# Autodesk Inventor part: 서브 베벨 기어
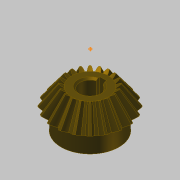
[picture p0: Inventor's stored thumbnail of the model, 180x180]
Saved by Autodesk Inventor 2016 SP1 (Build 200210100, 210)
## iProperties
Created: 2016-04
Part Number: 서브 베벨 기어
Material: 강철, 탄소
Document SubType Name: Modeling
Designer: mdu
Categories: <?xml version="1.0" encoding="UTF-16"?> <MemberInstance><Categories><FamilyTemplate><FamilyTemplateParameter ValueType="xs:double" Id="1" ObjectReferenceKey="da
Mass: 135.037 g
Surface Area: 63.6518 cm^2
Volume: 17.1585 cm^3
Density: 7.87 g/cm^3
Appearance: 얼룩무늬
CustomPartVersion: 1
Author: mdu
Revision Number: 1
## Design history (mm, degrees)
node "맨 위 점"
node "메쉬 평면2"
sketch "톱니 본체 스케치"
  geometry: L1 (0, 0)-(18.003, -31.331); L2 (18.003, -31.331)-(21.664, -28.891); L3 (21.664, -28.891)-(0, 0); L4 (20, -30)-(0, 0); L5 (10.813, -18.818)-(13.012, -17.352); L6 (18.003, -31.331)-(10.813, -18.818); L7 (21.664, -28.891)-(13.012, -17.352); L8 (0, -39.387)-(0, 6.564) reference; L9 (0, -30)-(21.664, -30)
  constraints: 16 end point, 4 point on line, 3 perpendicular, 2 collinear, 1 horizontal alignment, 1 vertical alignment
  dimensions: "d0" = 40 diameter of L4.start L8 (= da_de); "d1" = 36.00616 diameter of L1.end L8 (= da_dfe); "d2" = 43.3282 diameter of L2.end L8 (= da_dae); "d3" = 14.4 distance between parallel lines of L2 L5 (= da_b); "d4" = 28.8906 vertical distance of L2.end L1.start (= da_ve)
revolve "톱니 본체" sketch "톱니 본체 스케치" stored, may be unused: angle "d5" = 90 deg
node "시작점"
node "톱니 평면"
sketch "시작 스케치"
  geometry: L1 (0, -23.505)-(0, 10.645) reference; L2 (-0.834, -2.928)-(0.834, -2.928); A1 r 8.898 centre (-9.698, -3.713) between (-0.834, -2.928) and (-3.903, 3.04); A2 r 8.898 centre (9.698, -3.713) between (3.903, 3.04) and (0.834, -2.928); A3 r 27.357 centre (0, -24.037) between (3.903, 3.04) and (-3.903, 3.04); 1 further point
  constraints: 6 point on circle, 3 centre point, 3 symmetric about line, 2 end point, 1 coincident, 1 perpendicular, 1 other
  dimensions: "d7" = 8.89846 radius of A1 (= fd_rr); "d8" = 9.69794 horizontal distance of point (0, -24.037) A1.centre (= fd_x); "d9" = 20.32439 vertical distance of point (0, -24.037) A1.centre (= fd_y); "d57" = 27.35701 radius of A3 (= 0.5 x fd_dva + 0.3 x da_he); "d58" = 21.10901 distance from line of A3.centre L2 (= 0.5 x fd_dva - 1.12 x da_he)
node "끝점"
  node "끝 평면"
sketch "3D 스케치 오른쪽"
  node "Helical Curve Right" dims "d65" = 229.90621 (computed from da_dm, da_delta, da_beta), "d66" = 31.5, "d67" = 40 (= da_de), "d68" = -5.88003 (= -da_delta), "d69" = 12.16458 (computed from fd_loft, da_delta)
node "끝 평면 오른쪽"
sketch "끝 스케치 오른쪽"
  geometry: L1 (0, -22.649)-(0, 12.15) reference; L2 (-0.497, -1.72)-(0.497, -1.72); A1 r 5.299 centre (-5.775, -2.187) between (-0.497, -1.72) and (-2.324, 1.834); A2 r 5.299 centre (5.775, -2.187) between (2.324, 1.834) and (0.497, -1.72); A3 r 16.291 centre (0, -14.29) between (2.324, 1.834) and (-2.324, 1.834); 1 further point
  constraints: 6 point on circle, 3 centre point, 3 symmetric about line, 2 end point, 1 coincident, 1 perpendicular, 1 other
  dimensions: "d70" = 5.77526 horizontal distance of A3.centre A1.centre (computed from fd_x, fd_ratio); "d71" = 12.10346 vertical distance of point (0, -14.29) A1.centre (computed from fd_y, fd_ratio); "d72" = 5.29916 radius of A1 (computed from fd_rr, fd_ratio); "d73" = 12.57071 distance from line of point (0, -14.29) L2 (computed from d58, fd_ratio); "d74" = 16.29149 radius of A3 (computed from d57, fd_ratio)
feature "로프트 오른쪽" sketch "끝 스케치 오른쪽" dims "d75" = 0, "d77" = 0, "d79" = 0, "d80" = 90 deg, "d85" = 20, "d92" = 90 deg, "d93" = 90 deg, "da_teethtype" = 0 [user parameter]
sketch "3D 스케치 왼쪽"
  node "Helical Curve Left" dims "d26" = 229.90621 (computed from da_dm, da_delta, da_beta), "d27" = 12.16458 (computed from fd_loft, da_delta), "d28" = 40 (= da_de), "d29" = -5.88003 (= -da_delta)
node "끝 평면 왼쪽"
sketch "끝 스케치 왼쪽" dims "d56" = 10.82768 (derived)
  geometry: L1 (0, -35.087)-(0, 18.089) reference; L2 (-0.497, -1.716)-(0.497, -1.716); A1 r 5.299 centre (-5.775, -2.183) between (-0.497, -1.716) and (-2.324, 1.838); A2 r 5.299 centre (5.775, -2.183) between (2.324, 1.838) and (0.497, -1.716); A3 r 16.291 centre (0, -14.287) between (2.324, 1.838) and (-2.324, 1.838); 2 further points; 1 other entity
  constraints: 6 point on circle, 3 centre point, 3 symmetric about line, 2 end point, 1 coincident, 2 other
  dimensions: "d30" = 5.29916 radius of A1 (computed from fd_rr, fd_ratio); "d31" = 5.77526 horizontal distance of point (0, -14.287) A1.centre (computed from fd_x, fd_ratio); "d32" = 12.10346 vertical distance of A1.centre point (0, -14.287) (computed from fd_y, fd_ratio); "d61" = 16.29149 radius of A3 (computed from d57, fd_ratio); "d62" = 12.57071 distance from line of point (0, -14.287) L2 (computed from d58, fd_ratio)
feature "로프트 왼쪽" sketch "끝 스케치 왼쪽" dims "d35" = 0, "d37" = 0, "d39" = 0, "d40" = 90 deg, "d84" = 10, "d90" = 90 deg, "d91" = 90 deg, "da_teethtype" = 0 [user parameter]
sketch "본체 스케치"
  geometry: L1 (0, -35.038)-(0, -19.531) reference; L2 (18.003, -31.331)-(10.813, -18.818) reference; L3 (10.813, -18.818)-(0, -18.818); L4 (18.003, -31.331)-(0, -31.331)
  constraints: 4 end point, 2 perpendicular, 2 point on line
revolve "본체 고정" sketch "본체 스케치" stored, may be unused: angle "d46" = 90 deg
feature "피치 지름" dims angle "d47" = 90 deg
sketch "스케치8"
  geometry: C1 r 17 at (0, 0); 1 further point
  constraints: 1 centre point, 1 coincident
  dimensions: "d94" = 34 diameter of C1
extrude "돌출1" join sketch "스케치8" distance "d95" = 10; taper "d96" = 0 deg
sketch "스케치9"
  geometry: 1 further point
hole "구멍1" sketch "스케치9" at (0, 0) diameter "d97" = 12; stored, may be unused: countersink angle "d101" = 90 deg, drill point angle "d103" = 118 deg; dims "d98" = 6, "d99" = 4, "d100" = 2, "d102" = 8
sketch "스케치10"
  geometry: 1 further point
sketch "스케치11"
  geometry: 1 further point
sketch "스케치12"
  geometry: L1 (-2, 5.657)-(-2, 7.8); L2 (-2, 7.8)-(2, 7.8); L3 (2, 7.8)-(2, 5.657); A1 r 6 centre (0, 0) between (-2, 5.657) and (2, 5.657) reference; 1 further point
  constraints: 6 end point, 2 parallel, 2 point on circle, 1 perpendicular, 1 vertical
  dimensions: "d104" = 4 distance of L1.end L2.end; "d105" = 13.8 dimension on A1 L2
extrude "돌출2" cut sketch "스케치12" stored distance "d106" = 7; taper "d107" = 0 deg
chamfer "모따기1" distance "d108" = 1; stored, may be unused: second distance "d109" = 2, angle "d110" = 45 deg
body "Solid1"
feature "로프트" dims "d17" = 0, "d18" = 90 deg, "d19" = 0, "d20" = 90 deg, "d89" = 0, "da_teethtype" = 0 [user parameter]
pattern_circular "원형 패턴" dims angle "d22" = 360 deg, "d88" = 0, "da_teethtype" = 0 [user parameter]
pattern_circular "원형 패턴 오른쪽" dims angle "d82" = 360 deg, "da_teethtype" = 0 [user parameter]
pattern_circular "원형 패턴 왼쪽" dims angle "d42" = 360 deg, "da_teethtype" = 0 [user parameter]
sketch "끝 스케치"
  geometry: L1 (0, -15.359)-(0, 6.983) reference; L2 (-0.497, -1.72)-(0.497, -1.72); A1 r 5.299 centre (-5.775, -2.187) between (-0.497, -1.72) and (-2.324, 1.834); A2 r 5.299 centre (5.775, -2.187) between (2.324, 1.834) and (0.497, -1.72); A3 r 16.291 centre (0, -14.29) between (2.324, 1.834) and (-2.324, 1.834); 1 further point
  constraints: 6 point on circle, 3 centre point, 3 symmetric about line, 2 end point, 1 coincident, 1 other
  dimensions: "d12" = 5.29916 radius of A1 (computed from fd_rr, fd_ratio); "d15" = 5.77526 horizontal distance of A1.centre point (0, -14.29) (computed from fd_x, fd_ratio); "d16" = 12.10346 vertical distance of A1.centre point (0, -14.29) (computed from fd_y, fd_ratio); "d59" = 16.29149 radius of A3 (computed from d57, fd_ratio); "d60" = 12.57071 distance from line of A3.centre L2 (computed from d58, fd_ratio)
sketch "Sketch6"
  geometry: L1 (20, -30)-(0, 0) reference; L2 (0, -37.8)-(0, 6.3) reference
body "Srf1"
other parameters: "da_b" = 14.4 [user parameter; used in 2 equation terms], "da_de" = 40 [user parameter; used in 4 equation terms], "da_dae" = 43.3282 [user parameter; used in 2 equation terms], "da_dfe" = 36.00616 [user parameter; used in 1 equation term], "da_le" = 36.05551 [user parameter; used in 1 equation term], "da_omega" = 90 deg [user parameter; used in 1 equation term], "da_beta" = 0 [user parameter; used in 2 equation terms], "da_delta" = 5.88003 [user parameter; used in 8 equation terms], "da_alpha" = 20 deg [user parameter; used in 2 equation terms], "da_he" = 4.4 [user parameter; used in 4 equation terms], "da_ve" = 28.8906 [user parameter; used in 1 equation term], "fd_dv" = 48.07402 (computed from da_de, da_delta) [user parameter; used in 1 equation term], "fd_dva" = 52.07402 (computed from da_dae, da_delta) [user parameter; used in 3 equation terms], "fd_dvb" = 45.1748 (computed from fd_dv, da_alpha) [user parameter; used in 2 equation terms], "da_zv" = 240.37008 [user parameter; used in 1 equation term], "fd_loft" = 14.62 (= da_b + 0.05 x da_he) [user parameter; used in 4 equation terms], "fd_ratio" = 5.95514 (computed from da_le, fd_loft) [user parameter; used in 15 equation terms], "fd_rr" = 8.89846 (computed from fd_dd, fd_dvb) [user parameter; used in 6 equation terms], "fd_angle" = 0.66075 (computed from da_zv) [user parameter; used in 4 equation terms], "fd_x1" = 1.58709 (computed from da_dvw, fd_angle) [user parameter; used in 1 equation term], "fd_y1" = 23.98456 (computed from da_dvw, fd_angle) [user parameter; used in 1 equation term], "fd_x2" = 8.11084 (computed from fd_rr, fd_angle2, fd_angle) [user parameter; used in 1 equation term], "fd_y2" = 3.66016 (computed from fd_rr, fd_angle2, fd_angle) [user parameter; used in 1 equation term], "fd_x" = 9.69794 (= fd_x1 + fd_x2) [user parameter; used in 4 equation terms], "fd_y" = 20.32439 (= fd_y1 - fd_y2) [user parameter; used in 4 equation terms], "fd_angle2" = 3.57832 (computed from fd_dvb, fd_dd, da_alpha) [user parameter; used in 2 equation terms], "fd_dd" = 48.55402 (= fd_dva - 0.8 x da_he) [user parameter; used in 2 equation terms], "da_dvw" = 48.07402 [user parameter; used in 2 equation terms], "d11" = 14.62 (= fd_loft), "da_dm" = 32.01232 [user parameter; used in 2 equation terms], "da_x" = 0 [user parameter], "da_m" = 2 [user parameter], "d48" = 0, "d49" = 0, "d50" = 90 deg (= da_omega), "d51" = 9 deg (computed from da_z), "d52" = 0, "d53" = 0, "d54" = 0
